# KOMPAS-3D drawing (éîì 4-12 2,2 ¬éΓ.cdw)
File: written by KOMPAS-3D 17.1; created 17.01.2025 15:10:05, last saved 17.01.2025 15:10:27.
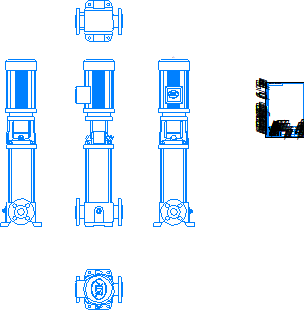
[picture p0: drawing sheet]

Sheet 1: A4, portrait

Title block, sheet 1: name: ВМН 4-12 2,2 кВт; designation: ВМН 4-12 2,2 кВт; sheets: 1; sheet format: A4; stored path: \\adlc.lan\data\АДЛ_ПКД\3D-модели\ADL production\Насосы ГРАНПАМП\Насосы ВМН\ВМН4\KOMPAS 2D\ВМН 4-12 2,2 кВт.cdw

Views: Вид 1, Спереди, Проекционный вид 2, Проекционный вид 3, Проекционный вид 4, Проекционный вид 5
Referenced files in \\adlc.lan\data\АДЛ_ПКД\3D-модели\ADL production\Насосы ГРАНПАМП\Насосы ВМН\ВМН4\KOMPAS 3D\: ВМН 4-12 2,2 кВт.m3d
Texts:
  Andrey
  АДЛ
Dimensions and other numbers on the sheet: 1:1; 1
